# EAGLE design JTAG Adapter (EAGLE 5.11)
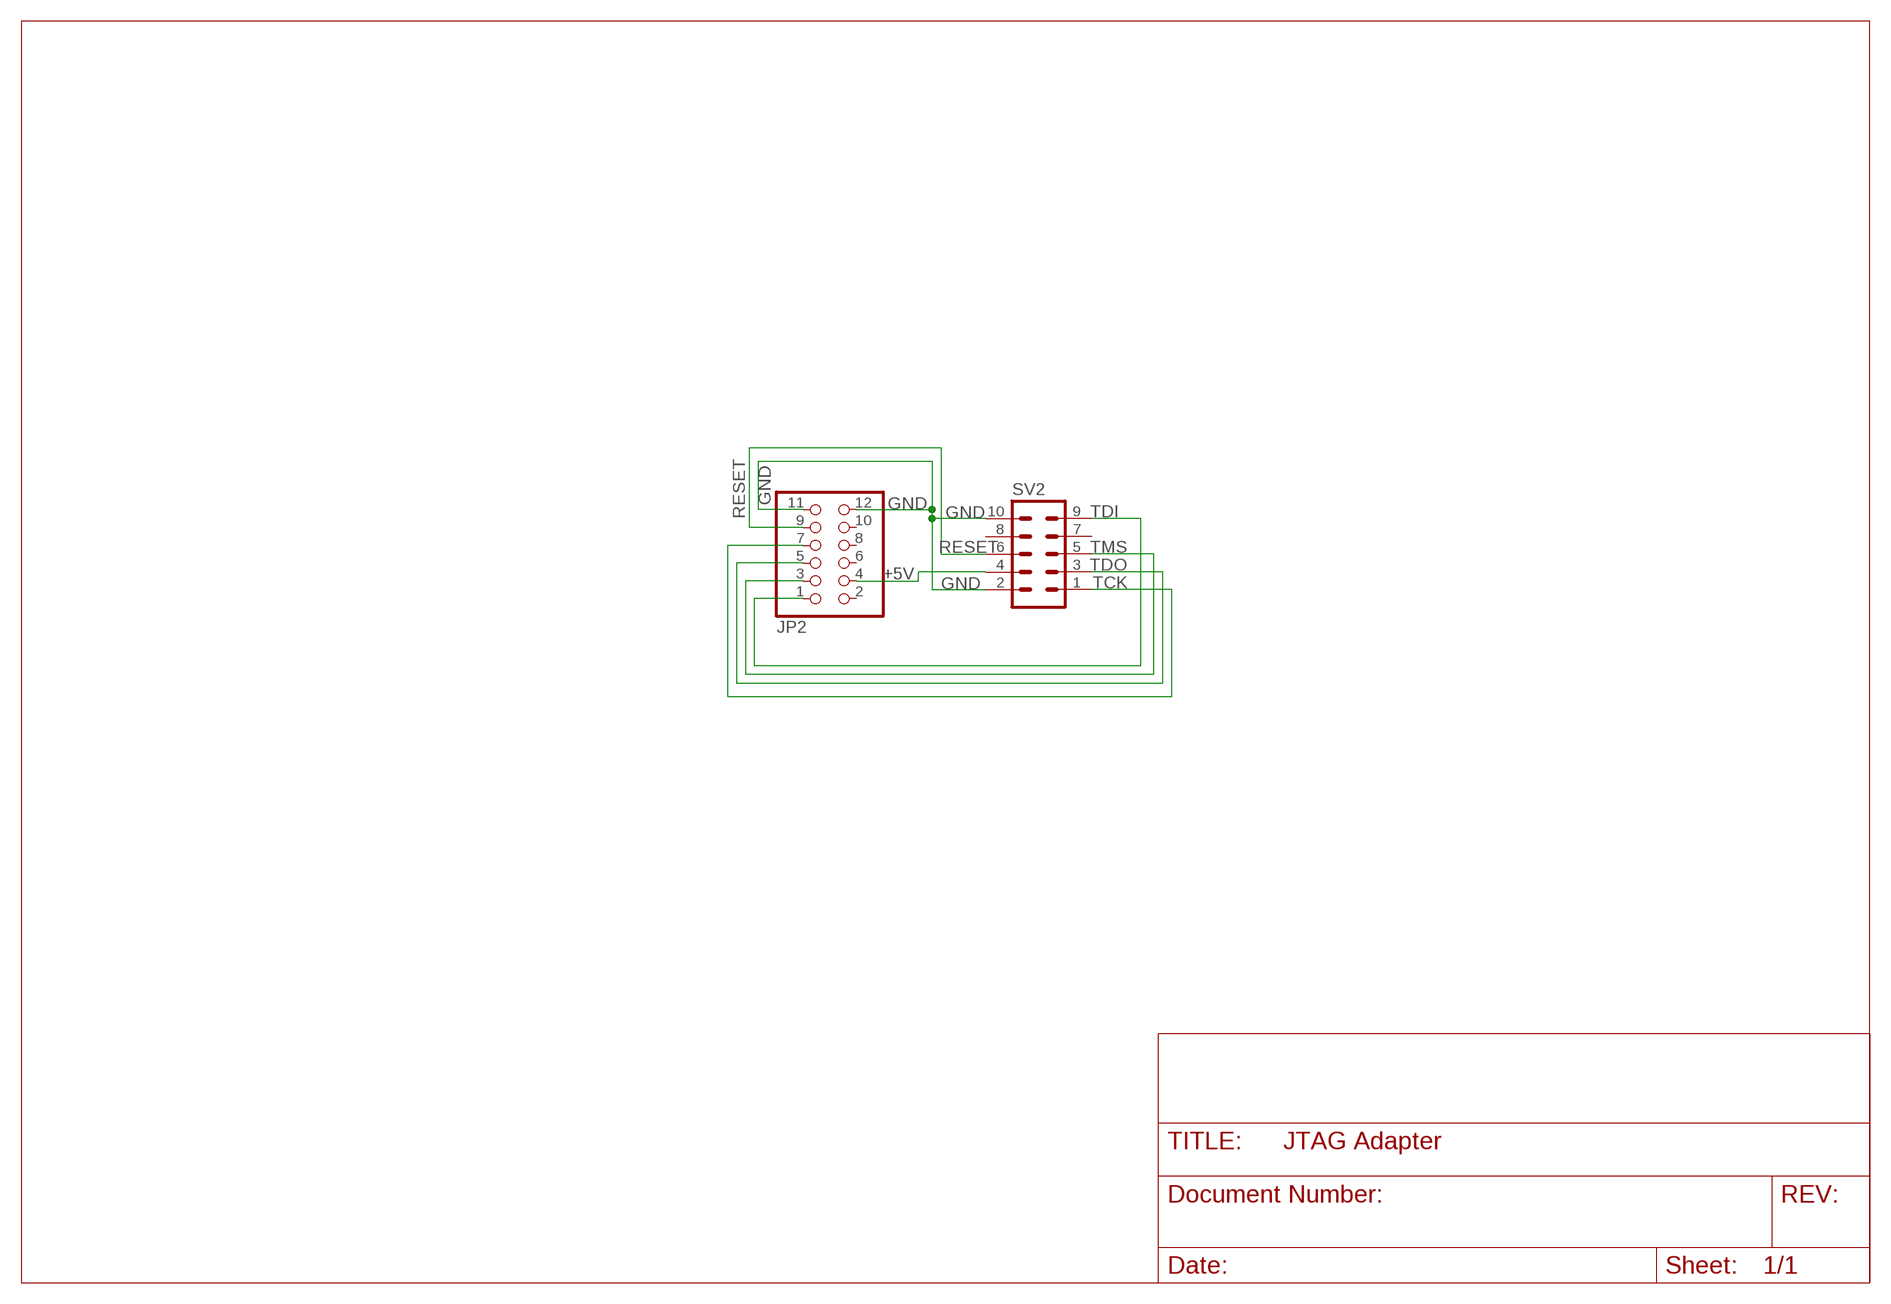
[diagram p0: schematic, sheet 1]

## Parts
JP2  PINHD-2X6  [2X06]
SV2  ML10  [ML10]

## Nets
+5V: JP2.4 SV2.4
GND: JP2.11 JP2.12 SV2.2 SV2.10
RESET: JP2.9 SV2.6
TCK: JP2.7 SV2.1
TDI: JP2.1 SV2.9
TDO: JP2.5 SV2.3
TMS: JP2.3 SV2.5
Unconnected: JP2.2 JP2.6 JP2.8 JP2.10 SV2.7 SV2.8

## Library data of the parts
JP2 = pinhead:PINHD-2X6: PIN HEADER
SV2 = con-harting-ml:ML10: HARTING

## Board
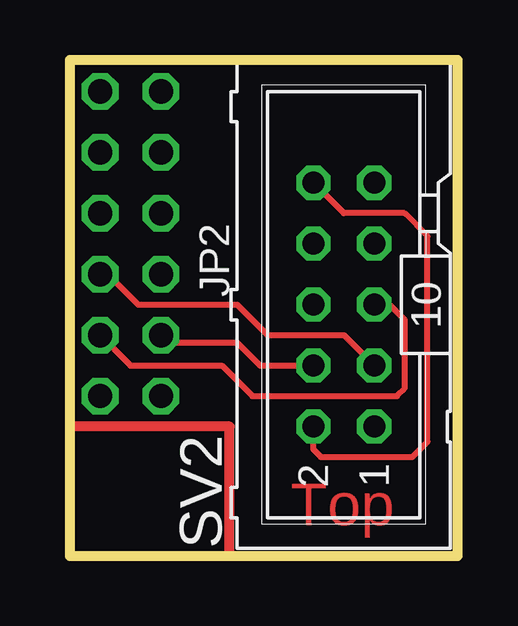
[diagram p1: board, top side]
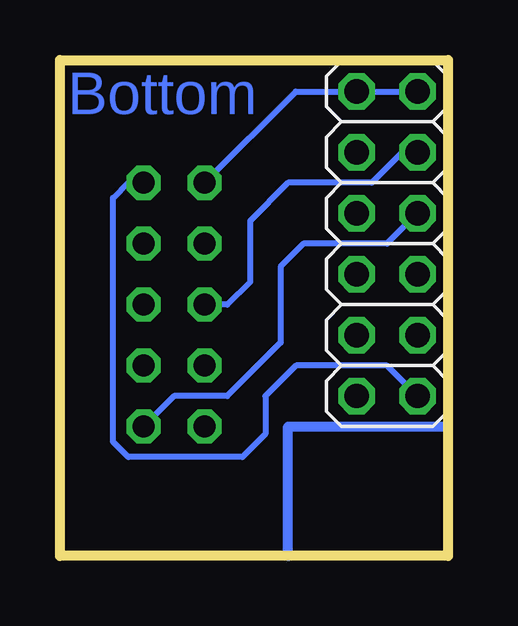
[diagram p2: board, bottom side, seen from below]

Size 16.18 x 20.68 mm. Coordinates in mm from the lower left corner, seen from the top.
Outline: 0,0 16.18,0 16.18,20.68 0,20.68 0,0
Copper layers (1*16): Top 0.035mm / dielectric 1.5mm / Bottom 0.035mm
Design rules "default": minimum track width 10mil, minimum drill 24mil, track to track 8mil, track to pad 8mil, pad to pad 8mil, via to via 8mil, smd to smd 8mil, copper to edge 40mil, drill to drill 8mil, minimum pad ring 10mil, minimum via ring 8mil, stop-mask expansion 4mil, vias tented up to drill 0mil, thermal gap 10mil

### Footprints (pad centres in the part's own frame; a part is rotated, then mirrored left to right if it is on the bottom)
2X06 = drill 1.016 octagon: 1 -6.35,-1.27; 2 -6.35,1.27; 3 -3.81,-1.27; 4 -3.81,1.27; 5 -1.27,-1.27; 6 -1.27,1.27; 7 1.27,-1.27; 8 1.27,1.27; 9 3.81,-1.27; 10 3.81,1.27; 11 6.35,-1.27; 12 6.35,1.27
ML10 = drill 0.914 octagon: 1 -5.08,-1.27; 2 -5.08,1.27; 3 -2.54,-1.27; 4 -2.54,1.27; 5 0,-1.27; 6 0,1.27; 7 2.54,-1.27; 8 2.54,1.27; 9 5.08,-1.27; 10 5.08,1.27

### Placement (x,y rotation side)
JP2  2.54,13.02 90 bottom
SV2  11.43,10.48 90 top

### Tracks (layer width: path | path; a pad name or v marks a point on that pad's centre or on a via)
+5V
  Top 0.254: SV2.4 7.94,7.94 6.99,8.89 3.81,8.89 JP2.4
GND
  Top 0.254: SV2.2 10.16,4.45 10.48,4.13 14.29,4.13 14.92,4.76 14.92,13.34 13.97,14.29 11.43,14.29 SV2.10
  Bottom 0.254: JP2.11 JP2.12 6.35,19.37 SV2.10
N$1
  Bottom 0.406: 0,5.4 6.67,5.4 6.67,0
N$2
  Top 0.406: 0,5.4 6.67,5.4 6.67,0
RESET
  Bottom 0.254: JP2.9 1.91,16.83 3.17,15.56 6.67,15.56 8.26,13.97 8.26,11.43 9.21,10.48 SV2.6
TCK
  Bottom 0.254: JP2.7 2.54,13.02 6.03,13.02 6.99,12.06 6.99,8.89 9.21,6.67 11.43,6.67 SV2.1
TDI
  Bottom 0.254: JP2.1 2.54,7.94 6.35,7.94 7.62,6.67 7.62,5.08 8.57,4.13 13.34,4.13 13.97,4.76 13.97,14.92 13.34,15.56 SV2.9
TDO
  Top 0.254: JP2.5 1.59,11.75 2.86,10.48 6.99,10.48 8.26,9.21 11.43,9.21 SV2.3
TMS
  Top 0.254: JP2.3 2.54,7.94 6.35,7.94 7.62,6.67 13.65,6.67 13.97,6.99 13.97,9.84 13.34,10.48 SV2.5

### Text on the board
Top: Top
Bottom: Bottom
